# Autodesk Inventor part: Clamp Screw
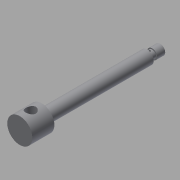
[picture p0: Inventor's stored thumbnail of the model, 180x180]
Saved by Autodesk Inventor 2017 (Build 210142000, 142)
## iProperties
Shininess: 77.0
Length Units: 11269
Angle Units: 11279
Time Units: 11290
Mass Units: 11283
Length Display Precision: 3
Angle Display Precision: 2
Created: 2002-02
Part Number: Clamp Screw
Document SubType Name: Modeling
Designer: ***
Density: 1 g/cm^3
Material: Generic
Mass: 23.4442 g
Surface Area: 81.4176 cm^2
Volume: 23.4442 cm^3
Appearance: Default
Density: 0.0
Volumn: 0.0
Area: 0.0
PropertySet Name: Model Information
Control State: 0
Master: False
Checked Out: False
Author: ***
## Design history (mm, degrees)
sketch "Sketch1"
  geometry: L1 (0, 140)-(5, 140); L2 (5, 140)-(5, 132); L3 (5, 132)-(4, 132); L4 (4, 132)-(4, 127); L5 (4, 127)-(6.5, 127); L6 (6.5, 127)-(6.5, 25); L7 (6.5, 25)-(4, 25); L8 (4, 25)-(4, 22); L9 (4, 22)-(12.5, 22); L10 (12.5, 22)-(12.5, 0); L11 (12.5, 0)-(0, 0); L12 (0, 0)-(0, 140)
  constraints: 24 end point, 10 parallel, 1 horizontal, 1 perpendicular
  dimensions: "d0" = 10 diameter of L2 L12; "d1" = 8 diameter of L4 L12; "d2" = 13 diameter of L6 L12; "d3" = 8 diameter of L7.end L12; "d4" = 25 diameter of L10 L12; "d5" = 3 distance from line of L7.end L9; "d6" = 8 distance of L1.end L2.end; "d7" = 13 vertical distance of L1.end L5.end; "d8" = 22 distance of L9.end L10.end; "d10" = 102 distance of L5.end L6.end
revolve "Revolution1" sketch "Sketch1" stored, may be unused: angle "d11" = 90 deg
sketch "Sketch3"
  geometry: L1 (-12.5, 0)-(12.5, 0) reference; C1 r 5 at (-0.113, 11)
  constraints: 1 centre point
  dimensions: "d13" = 10 diameter of C1; "d14" = 11 distance from line of L1 C1.centre
extrude "Extrusion1" cut sketch "Sketch3" stored distance "d15" = 10; taper "d16" = 0 deg
sketch "Sketch4"
  geometry: L1 (0, 138.841)-(0, 0); L2 (-12.5, 0)-(12.5, 0) reference; L3 (-5, 140)-(5, 140) reference; C1 r 1 at (0, 129.5)
  constraints: 2 end point, 1 centre point, 1 point on line, 1 vertical
  dimensions: "d17" = 2 diameter of C1; "d18" = 10.5 distance from line of L3 C1.centre
extrude "Extrusion2" cut sketch "Sketch4" stored distance "d19" = 10; taper "d20" = 0 deg
body "Solid1"
